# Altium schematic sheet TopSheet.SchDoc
size 431 x 279 mm; Date: Not shown in title block; ApprovedBy: Not shown in title block; CheckedBy: Not shown in title block; Author: Not shown in title block; CompanyName: Not shown in title block; Engineer: Not shown in title block; Organization: Not shown in title block; Address1: Not shown in title block; Address2: Not shown in title block; Address3: Not shown in title block; Address4: Not shown in title block; DocumentNumber: 6; Revision: Use project parameter SCH_Rev; SheetNumber: 6; SheetTotal: 6; PageSetup: Record=PageOptions¦CenterHorizontal=True¦CenterVertical=True¦PrintScale=1.00¦XCorrection=1.00¦YCorrection=1.00¦PrintKind=0¦BorderSize=5000000¦LeftOffset=0¦BottomOffset=0¦Orientation=2¦PaperLength=1000¦PaperWidth=1000¦Scale=100¦PaperSource=15¦PrintQuality=600¦MediaType=1¦DitherType=10¦PaperKind=Letter¦PrintScaleMode=1
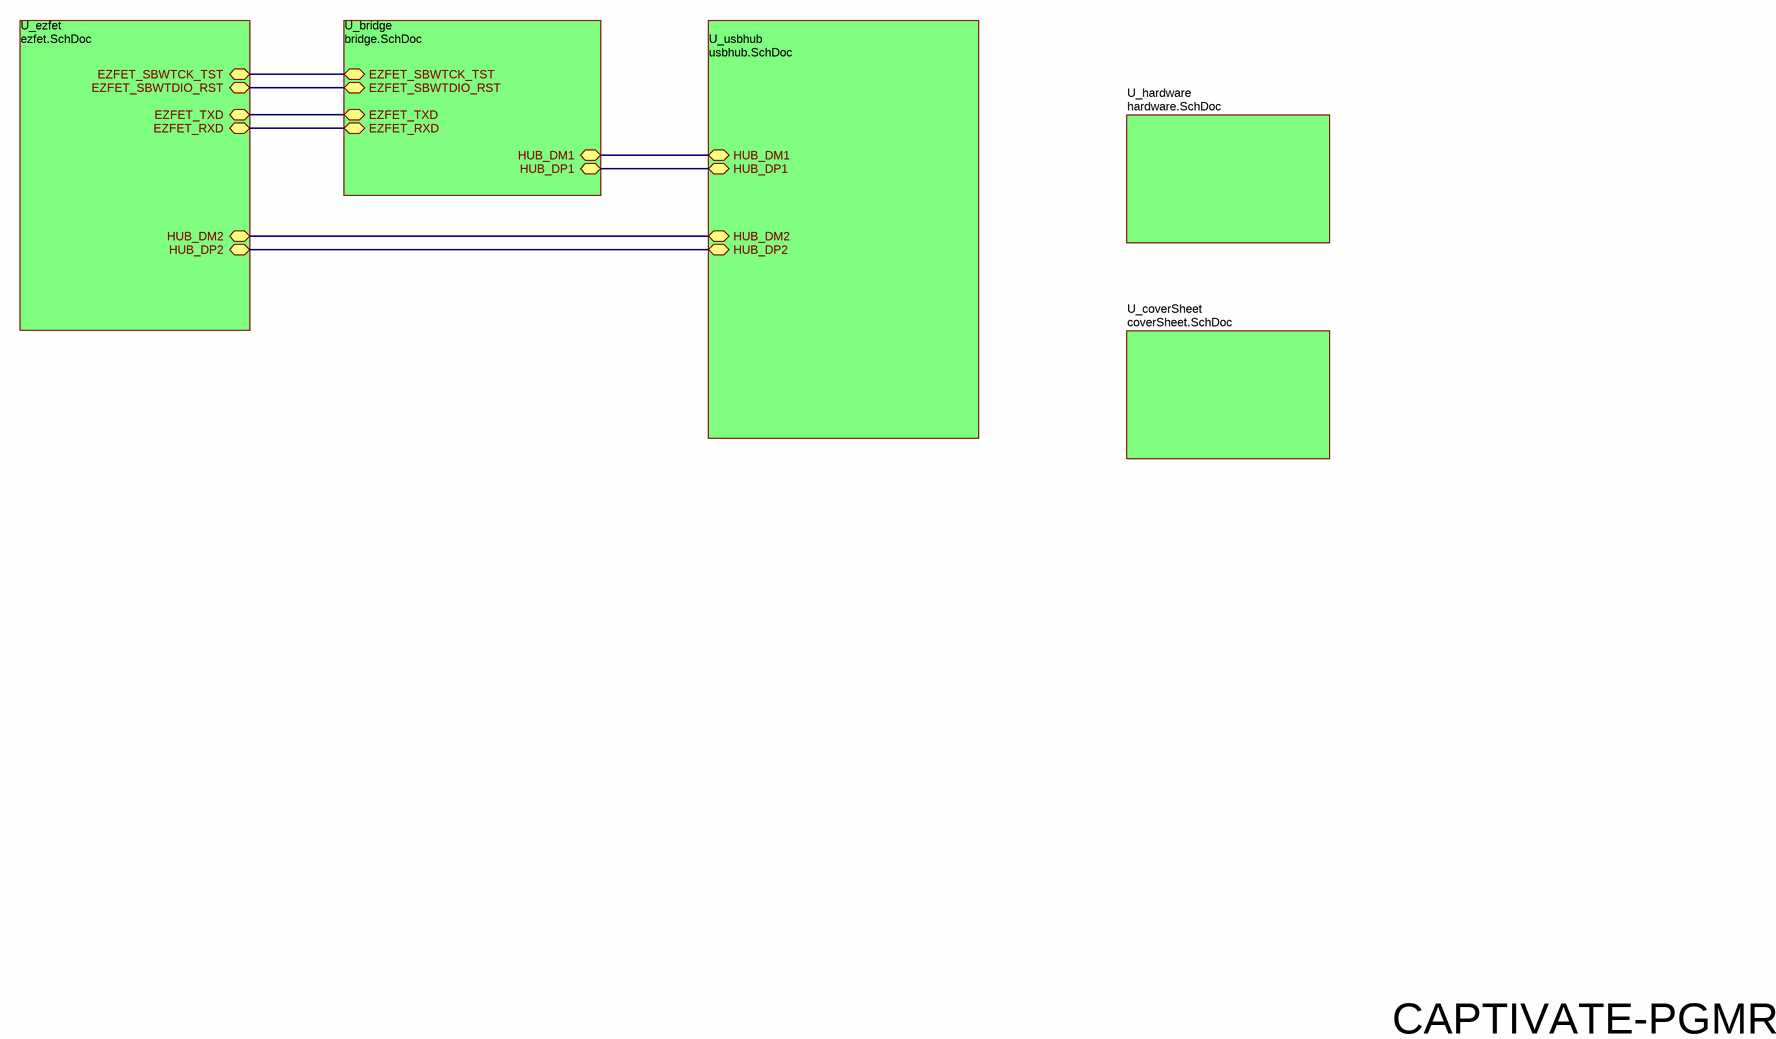
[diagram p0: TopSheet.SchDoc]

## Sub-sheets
U_bridge = bridge.SchDoc: EZFET_SBWTCK_TST, EZFET_SBWTDIO_RST, EZFET_TXD (bidir), EZFET_RXD (bidir), HUB_DM1 (bidir), HUB_DP1 (bidir)
U_coverSheet = coverSheet.SchDoc: no entries
U_ezfet = ezfet.SchDoc: EZFET_SBWTDIO_RST, EZFET_SBWTCK_TST, EZFET_TXD (bidir), EZFET_RXD (bidir), HUB_DM2 (bidir), HUB_DP2 (bidir)
U_hardware = hardware.SchDoc: no entries
U_usbhub = usbhub.SchDoc: HUB_DM2 (bidir), HUB_DP2 (bidir), HUB_DM1 (bidir), HUB_DP1 (bidir)

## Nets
(unnamed): sheet U_usbhub/HUB_DM2, sheet U_ezfet/HUB_DM2
(unnamed): sheet U_usbhub/HUB_DP2, sheet U_ezfet/HUB_DP2  [a separate net that carries the same name]
(unnamed): sheet U_usbhub/HUB_DM1, sheet U_bridge/HUB_DM1  [a separate net that carries the same name]
(unnamed): sheet U_usbhub/HUB_DP1, sheet U_bridge/HUB_DP1  [a separate net that carries the same name]
(unnamed): sheet U_ezfet/EZFET_SBWTDIO_RST, sheet U_bridge/EZFET_SBWTDIO_RST  [a separate net that carries the same name]
(unnamed): sheet U_ezfet/EZFET_SBWTCK_TST, sheet U_bridge/EZFET_SBWTCK_TST  [a separate net that carries the same name]
(unnamed): sheet U_ezfet/EZFET_TXD, sheet U_bridge/EZFET_TXD  [a separate net that carries the same name]
(unnamed): sheet U_ezfet/EZFET_RXD, sheet U_bridge/EZFET_RXD  [a separate net that carries the same name]

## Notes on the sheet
- CAPTIVATE-PGMR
